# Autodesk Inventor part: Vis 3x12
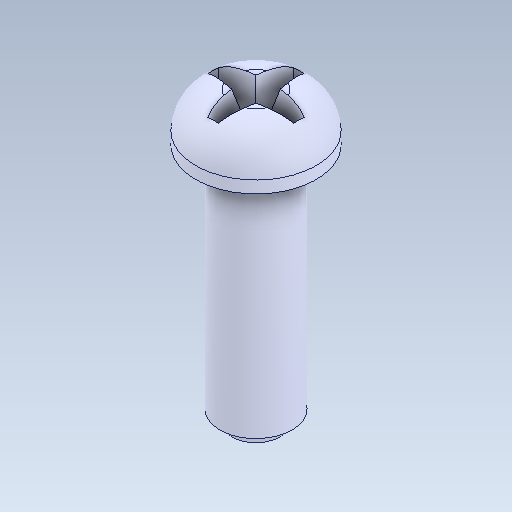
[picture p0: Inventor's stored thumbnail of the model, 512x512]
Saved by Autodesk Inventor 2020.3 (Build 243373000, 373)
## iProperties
Created: 2018-09
Part Number: Vis 3x12
Material: Générique
Document SubType Name: Modeling
Designer: ficho
Density: 1 g/cm^3
Appearance: Par défaut
Mass: 0.098445 g
Surface Area: 1.63535 cm^2
Volume: 0.098445 cm^3
Sending System: SolidWorks 2015
Last Author: adrien
Last Saved: 2019-01-11
Author: ficho
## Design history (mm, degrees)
feature "Enlèv. mat.-Extru.1"
node "Solide1"
